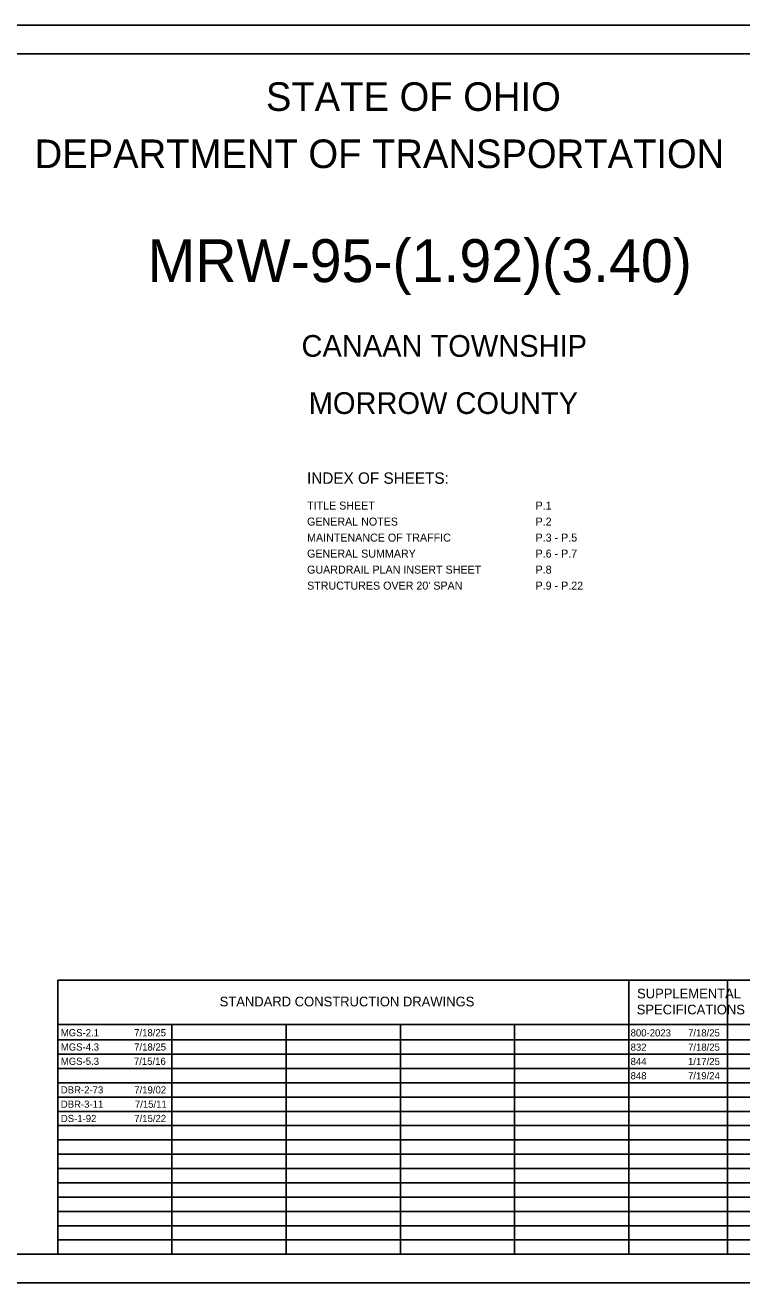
# Model space of a CAD drawing. Extents: x 0 to 34, y 0 to 22.
# Drawn here: x 9.58 to 22.13, y 0 to 22 of the extents above; entities that cross this region are included whole.
import ezdxf

# ---------------------------------------------------------------- set-up
doc = ezdxf.new("R2010")
doc.units = 0
for name, color, linetype in [('Default', 7, 'Continuous'), ('SH_Border', 7, 'Continuous'), ('SH_Cut_Line', 7, 'Continuous'), ('SH_Data', 7, 'Continuous'), ('SH_Text', 7, 'Continuous')]:
    doc.layers.add(name, color=color, linetype=linetype)

msp = doc.modelspace()

# ---------------------------------------------------------------- linework, layer by layer
at = {"layer": 'SH_Cut_Line'}
for p, q in [((10.15, 5.292), (23.6, 5.292)), ((10.15, 0.5), (10.15, 5.292)), ((20.15, 0.5), (20.15, 5.292)), ((21.875, 0.5), (21.875, 5.292)), ((10.15, 4.521), (23.6, 4.521)), ((12.15, 0.5), (12.15, 4.521)), ((14.15, 0.5), (14.15, 4.521)), ((16.15, 0.5), (16.15, 4.521)), ((18.15, 0.5), (18.15, 4.521)), ((10.15, 4.25), (23.6, 4.25)), ((10.15, 4), (23.6, 4)), ((10.15, 3.75), (23.6, 3.75)), ((10.15, 3.5), (23.6, 3.5)), ((10.15, 3.25), (23.6, 3.25)), ((10.15, 3), (23.6, 3)), ((10.15, 2.75), (23.6, 2.75)), ((10.15, 2.5), (23.6, 2.5)), ((10.15, 2.25), (23.6, 2.25)), ((10.15, 2), (23.6, 2)), ((10.15, 1.75), (23.6, 1.75)), ((10.15, 1.5), (23.6, 1.5)), ((10.15, 1.25), (23.6, 1.25)), ((10.15, 1), (23.6, 1)), ((10.15, 0.75), (23.6, 0.75))]:
    msp.add_line(p, q, dxfattribs=at)
at = {"layer": 'SH_Data'}
msp.add_lwpolyline([(1.5, 21.5), (33.5, 21.5), (33.5, 0.5), (1.5, 0.5)], close=True, dxfattribs=at)
at = {"layer": 'SH_Text'}
msp.add_lwpolyline([(0, 0), (34, 0), (34, 22), (0, 22)], close=True, dxfattribs=at)

# ---------------------------------------------------------------- texts
at = {"layer": 'Default'}
for s, p in [('MGS-2.1', (10.205, 4.313)), ('7/18/25', (11.489, 4.313)), ('MGS-4.3', (10.205, 4.063)), ('7/18/25', (11.489, 4.063)), ('MGS-5.3', (10.205, 3.813)), ('7/15/16', (11.485, 3.813)), ('DBR-2-73', (10.205, 3.313)), ('7/19/02', (11.491, 3.313)), ('DBR-3-11', (10.205, 3.063)), ('7/15/11', (11.502, 3.063)), ('DS-1-92', (10.205, 2.813)), ('7/15/22', (11.491, 2.813))]:
    msp.add_text(s, height=0.125, dxfattribs=at).set_placement(p)
at = {"layer": 'SH_Border'}
for s, height, p in [('STATE OF OHIO', 0.5, (13.795, 20.5)), ('DEPARTMENT OF TRANSPORTATION', 0.5, (9.747, 19.5)), ('MRW-95-(1.92)(3.40)', 0.75, (11.722, 17.505)), ('CANAAN TOWNSHIP', 0.38, (14.419, 16.199)), ('MORROW COUNTY', 0.38, (14.545, 15.199)), ('INDEX OF SHEETS:', 0.2, (14.516, 13.977)), ('TITLE SHEET                         ', 0.14, (14.516, 13.526)), ('P.1', 0.14, (18.516, 13.526)), ('GENERAL NOTES', 0.14, (14.516, 13.246)), ('P.2', 0.14, (18.516, 13.246)), ('MAINTENANCE OF TRAFFIC', 0.14, (14.516, 12.966)), ('P.3 - P.5', 0.14, (18.516, 12.966)), ('GENERAL SUMMARY', 0.14, (14.516, 12.686)), ('P.6 - P.7', 0.14, (18.516, 12.686)), ('GUARDRAIL PLAN INSERT SHEET', 0.14, (14.516, 12.406)), ('P.8', 0.14, (18.516, 12.406)), ("STRUCTURES OVER 20' SPAN            ", 0.14, (14.516, 12.126)), ('P.9 - P.22', 0.14, (18.516, 12.126)), ('SUPPLEMENTAL', 0.17, (20.293, 4.976)), ('STANDARD CONSTRUCTION DRAWINGS', 0.17, (12.986, 4.836)), ('SPECIFICATIONS', 0.17, (20.287, 4.696)), ('800-2023', 0.125, (20.18, 4.31)), ('7/18/25', 0.125, (21.185, 4.31)), ('832', 0.125, (20.18, 4.06)), ('7/18/25', 0.125, (21.185, 4.06)), ('844', 0.125, (20.18, 3.81)), ('1/17/25', 0.125, (21.185, 3.81)), ('848', 0.125, (20.18, 3.56)), ('7/19/24', 0.125, (21.185, 3.56))]:
    msp.add_text(s, height=height, dxfattribs=at).set_placement(p)

doc.saveas('drawing.dxf')
